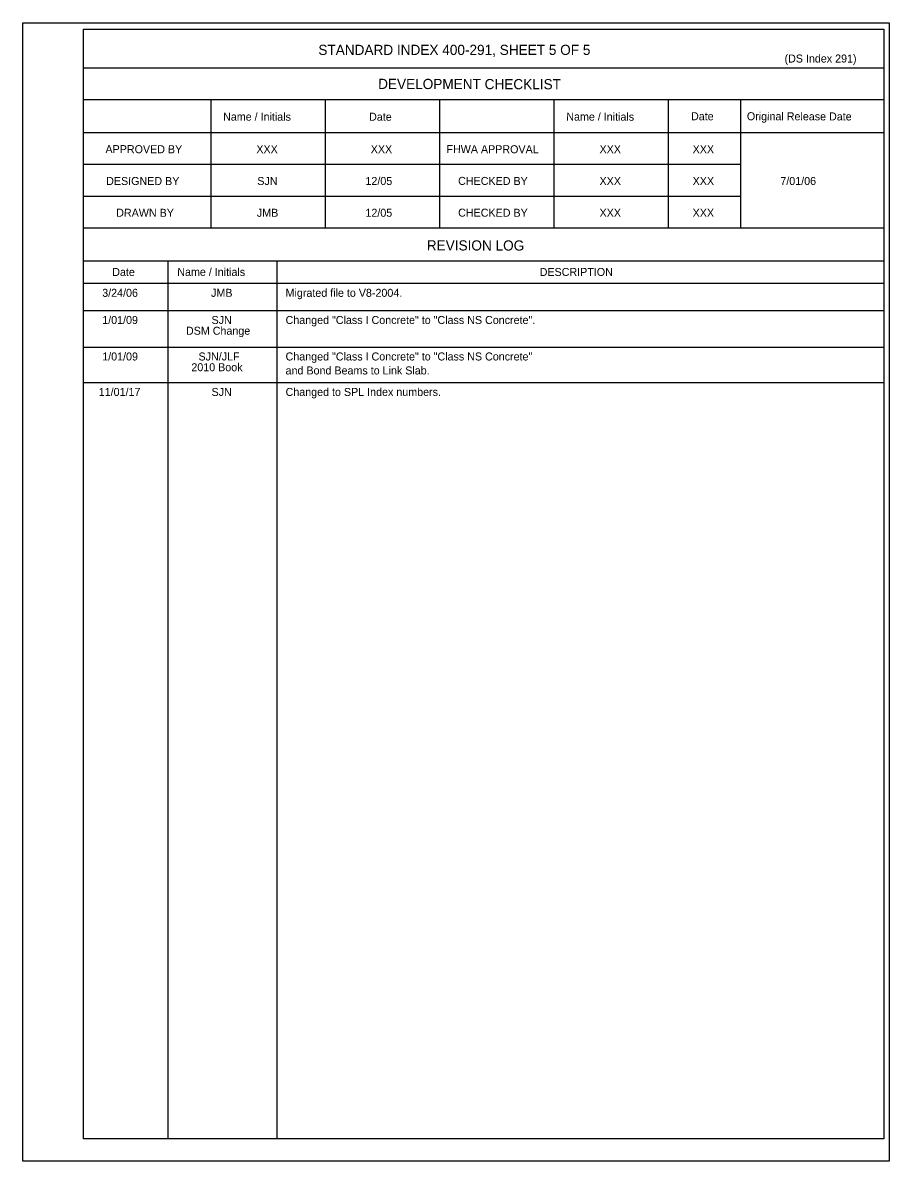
# Model space of a CAD drawing. Extents: x 10691 to 11555, y 76323 to 76455.
# Drawn here: x 10727.82 to 10744.18, y 76426.36 to 76447.86 of the extents above; entities that cross this region are included whole.
import ezdxf

# ---------------------------------------------------------------- set-up
doc = ezdxf.new("R2010")
doc.units = 0
for name, color, linetype in [('Border', 7, 'Continuous'), ('Patterning', 7, 'Continuous'), ('PlotBorder_dp', 7, 'Continuous'), ('TextMisc', 7, 'Continuous')]:
    doc.layers.add(name, color=color, linetype=linetype)

msp = doc.modelspace()

# ---------------------------------------------------------------- linework, layer by layer
at = {"layer": 'Border'}
for p, q in [((10744.074, 76447.007), (10728.964, 76447.007)), ((10744.074, 76446.407), (10728.964, 76446.407)), ((10731.364, 76446.407), (10731.364, 76443.986)), ((10733.524, 76446.407), (10733.524, 76443.986)), ((10735.684, 76446.407), (10735.684, 76443.986)), ((10737.844, 76446.407), (10737.844, 76443.986)), ((10740.004, 76446.407), (10740.004, 76443.986)), ((10741.365, 76446.407), (10741.365, 76443.986)), ((10744.074, 76445.786), (10728.964, 76445.786)), ((10741.365, 76445.186), (10728.964, 76445.186)), ((10741.365, 76444.586), (10728.964, 76444.586)), ((10744.074, 76443.986), (10728.964, 76443.986)), ((10744.074, 76443.365), (10728.964, 76443.365)), ((10730.554, 76443.365), (10730.554, 76426.786)), ((10732.611, 76443.365), (10732.611, 76426.786)), ((10744.074, 76442.943), (10728.964, 76442.943))]:
    msp.add_line(p, q, dxfattribs=at)
msp.add_lwpolyline([(10728.964, 76447.743), (10744.074, 76447.743), (10744.074, 76426.786), (10728.964, 76426.786)], close=True, dxfattribs=at)
at = {"layer": 'PlotBorder_dp'}
msp.add_line((10727.816, 76426.365), (10727.816, 76426.365), dxfattribs=at)
msp.add_lwpolyline([(10727.816, 76447.865), (10744.176, 76447.865), (10744.176, 76426.365), (10727.816, 76426.365)], close=True, dxfattribs=at)
at = {"layer": 'TextMisc'}
for p, q in [((10728.964, 76442.429), (10744.074, 76442.429)), ((10728.964, 76441.74), (10744.074, 76441.74)), ((10728.964, 76441.07), (10744.074, 76441.07))]:
    msp.add_line(p, q, dxfattribs=at)

# ---------------------------------------------------------------- texts
at = {"layer": 'Patterning'}
for s, height, p in [('STANDARD INDEX 400-291, SHEET 5 OF 5', 0.192, (10733.397, 76447.257)), ('XXX', 0.1512, (10732.226, 76445.401)), ('XXX', 0.1512, (10734.386, 76445.401)), ('XXX', 0.1512, (10738.706, 76445.401)), ('XXX', 0.1512, (10740.464, 76445.401)), ('SJN', 0.1512, (10732.244, 76444.801)), ('12/05', 0.1512, (10734.286, 76444.801)), ('XXX', 0.1512, (10738.706, 76444.801)), ('XXX', 0.1512, (10740.464, 76444.801)), ('7/01/06', 0.1512, (10742.12, 76444.801)), ('JMB', 0.1512, (10732.236, 76444.201)), ('12/05', 0.1512, (10734.286, 76444.201)), ('XXX', 0.1512, (10738.706, 76444.201)), ('XXX', 0.1512, (10740.464, 76444.201)), ('DESCRIPTION', 0.1512, (10737.576, 76443.083)), ('3/24/06', 0.1512, (10729.316, 76442.689)), ('JMB', 0.1512, (10731.371, 76442.689)), ('Migrated file to V8-2004.', 0.1512, (10732.778, 76442.689)), ('1/01/09', 0.1512, (10729.316, 76442.176)), ('SJN', 0.1512, (10731.38, 76442.176)), ('Changed "Class I Concrete" to "Class NS Concrete".', 0.1512, (10732.778, 76442.176)), ('DSM Change', 0.1512, (10730.897, 76441.973)), ('1/01/09', 0.1512, (10729.316, 76441.487)), ('SJN/JLF', 0.1512, (10731.134, 76441.487)), ('Changed "Class I Concrete" to "Class NS Concrete"', 0.1512, (10732.778, 76441.487)), ('2010 Book', 0.1512, (10730.999, 76441.284)), ('and Bond Beams to Link Slab.', 0.1512, (10732.778, 76441.223)), ('11/01/17', 0.1512, (10729.25, 76440.817)), ('SJN', 0.1512, (10731.38, 76440.817)), ('Changed to SPL Index numbers.', 0.1512, (10732.778, 76440.817))]:
    msp.add_text(s, height=height, dxfattribs=at).set_placement(p)
for s, height, p in [('DEVELOPMENT CHECKLIST', 0.192, (10734.525, 76446.615)), ('Name / Initials', 0.1512, (10731.598, 76446.017)), ('Date', 0.1512, (10734.354, 76446.015)), ('Name / Initials', 0.1512, (10738.078, 76446.017)), ('Date', 0.1512, (10740.433, 76446.024)), ('Original Release Date', 0.1512, (10741.488, 76446.024)), ('APPROVED BY', 0.1512, (10729.377, 76445.403)), ('FHWA APPROVAL', 0.1512, (10735.815, 76445.403)), ('DESIGNED BY', 0.1512, (10729.39, 76444.802)), ('CHECKED BY', 0.1512, (10736.036, 76444.803)), ('DRAWN BY', 0.1512, (10729.58, 76444.202)), ('CHECKED BY', 0.1512, (10736.036, 76444.203)), ('REVISION LOG', 0.192, (10735.444, 76443.566)), ('Date', 0.1512, (10729.505, 76443.083)), ('Name / Initials', 0.1512, (10730.733, 76443.085))]:
    msp.add_text(s, height=height, rotation=359.8756, dxfattribs=at).set_placement(p)
at = {"layer": 'TextMisc'}
msp.add_text('(DS Index 291)', height=0.1512, dxfattribs=at).set_placement((10742.199, 76447.114))

doc.saveas('drawing.dxf')
